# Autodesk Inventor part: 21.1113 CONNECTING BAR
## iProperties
Created: 2007-01
Part Number: 21.1113 CONNECTING BAR
Material: Steel
Document SubType Name: Modeling
Designer: Andy Moles
Density: 7.85 g/cm^3
Author: Andy Moles
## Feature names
1. Base1
2. Hole1
